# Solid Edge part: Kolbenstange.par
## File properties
Username: ahadarics
Dokumentum tartalom típus: 0
Author: ahadarics
Last saved by: ahadarics
Revision: 83
Sűrűség: 0,000 kg/m^3
Pontosság: 0,990
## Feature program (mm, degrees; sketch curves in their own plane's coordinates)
base feature "unnamed BaseFeature 1"
thread "unnamed Thread 1"
chamfer "unnamed Chamfer 1"
sketch for "Kihúzás_1" plane through (60, 0, 0) normal (1, 0, 0) x-axis (0, 0, 1)
  circle centre (0, 0) radius 10
extrude "Kihúzás_1" add finite 26.5 along -normal
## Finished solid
Body 1: solid body, 18 faces, 34 edges, 18 vertices.
  Faces by surface: plane 9, cone 7, cylinder 2
  Edges by curve: line 12, spline 12, circle 10
Bounding box of the edges (mm): 293.500 x 20.000 x 20.000, from (-233.5, -10, -10) to (60, 10, 10).
Cylindrical faces by radius (mm): R4 x1, R10 x1
Conical faces (half-angle, radius in mm at the cone's reference point): 30 deg R5.75 x6, 45 deg R3.3 x1
Planar faces by outward normal: +x 1, +y 1, -x 2, -y 1, oblique 4
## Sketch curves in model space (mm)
circle centre (60, 0, 0) radius 10
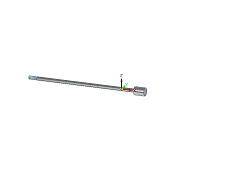
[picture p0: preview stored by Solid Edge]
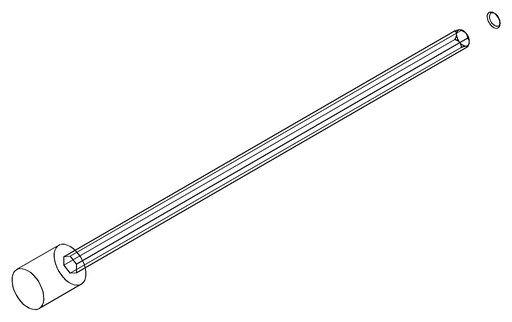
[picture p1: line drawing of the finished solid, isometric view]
